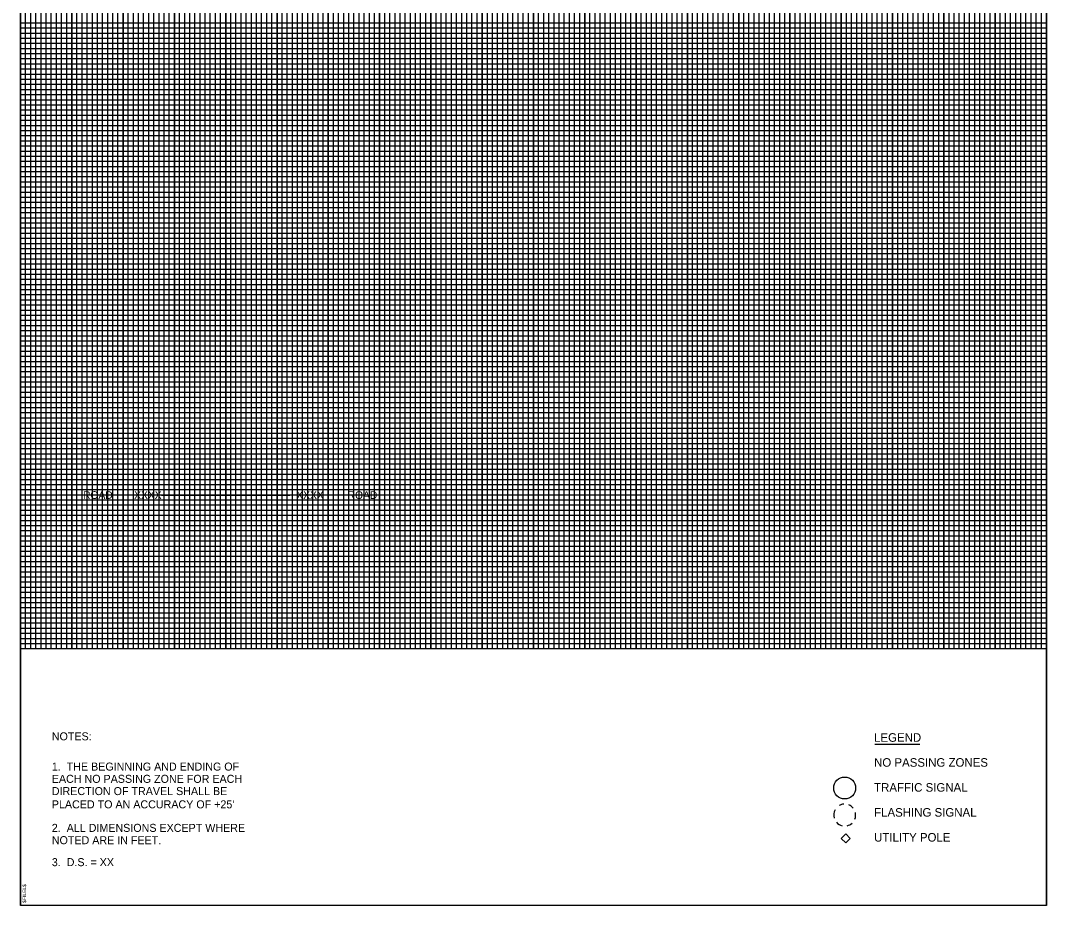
# Model space of a CAD drawing. Extents: x -6359 to 1641, y 3001 to 24737.
# Drawn here: x -6359 to 1641, y 10898 to 17798 of the extents above; entities that cross this region are included whole.
import ezdxf

# ---------------------------------------------------------------- set-up
doc = ezdxf.new("R2010")
doc.units = 0
for name, color, linetype in [('_grid', 7, 'Continuous'), ('_Notes', 7, 'Continuous'), ('Border', 7, 'Continuous'), ('TB - ON', 7, 'Continuous'), ('Title Block', 7, 'Continuous')]:
    doc.layers.add(name, color=color, linetype=linetype)

msp = doc.modelspace()

# ---------------------------------------------------------------- linework, layer by layer
at = {"layer": '_grid'}
for p, q in [((-6358.7, 21698.2), (-6358.7, 12898.2)), ((-6318.7, 12898.2), (-6318.7, 21698.2)), ((-6278.7, 12898.2), (-6278.7, 21698.2)), ((-6238.7, 12898.2), (-6238.7, 21698.2)), ((-6198.7, 12898.2), (-6198.7, 21698.2)), ((-6158.7, 12898.2), (-6158.7, 21698.2)), ((-6118.7, 12898.2), (-6118.7, 21698.2)), ((-6078.7, 12898.2), (-6078.7, 21698.2)), ((-6038.7, 12898.2), (-6038.7, 21698.2)), ((-5998.7, 12898.2), (-5998.7, 21698.2)), ((-5958.7, 21698.2), (-5958.7, 12898.2)), ((-5958.7, 12898.2), (-5958.7, 21698.2)), ((-5918.7, 12898.2), (-5918.7, 21698.2)), ((-5878.7, 12898.2), (-5878.7, 21698.2)), ((-5838.7, 12898.2), (-5838.7, 21698.2)), ((-5798.7, 12898.2), (-5798.7, 21698.2)), ((-5758.7, 12898.2), (-5758.7, 21698.2)), ((-5718.7, 12898.2), (-5718.7, 21698.2)), ((-5678.7, 12898.2), (-5678.7, 21698.2)), ((-5638.7, 12898.2), (-5638.7, 21698.2)), ((-5598.7, 12898.2), (-5598.7, 21698.2)), ((-5558.7, 21698.2), (-5558.7, 12898.2)), ((-5558.7, 12898.2), (-5558.7, 21698.2)), ((-5518.7, 12898.2), (-5518.7, 21698.2)), ((-5478.7, 12898.2), (-5478.7, 21698.2)), ((-5438.7, 12898.2), (-5438.7, 21698.2)), ((-5398.7, 12898.2), (-5398.7, 21698.2)), ((-5358.7, 12898.2), (-5358.7, 21698.2)), ((-5318.7, 12898.2), (-5318.7, 21698.2)), ((-5278.7, 12898.2), (-5278.7, 21698.2)), ((-5238.7, 12898.2), (-5238.7, 21698.2)), ((-5198.7, 12898.2), (-5198.7, 21698.2)), ((-5158.7, 21698.2), (-5158.7, 12898.2)), ((-5158.7, 12898.2), (-5158.7, 21698.2)), ((-5118.7, 12898.2), (-5118.7, 21698.2)), ((-5078.7, 12898.2), (-5078.7, 21698.2)), ((-5038.7, 12898.2), (-5038.7, 21698.2)), ((-4998.7, 12898.2), (-4998.7, 21698.2)), ((-4958.7, 12898.2), (-4958.7, 21698.2)), ((-4918.7, 12898.2), (-4918.7, 21698.2)), ((-4878.7, 12898.2), (-4878.7, 21698.2)), ((-4838.7, 12898.2), (-4838.7, 21698.2)), ((-4798.7, 12898.2), (-4798.7, 21698.2)), ((-4758.7, 21698.2), (-4758.7, 12898.2)), ((-4758.7, 12898.2), (-4758.7, 21698.2)), ((-4718.7, 12898.2), (-4718.7, 21698.2)), ((-4678.7, 12898.2), (-4678.7, 21698.2)), ((-4638.7, 12898.2), (-4638.7, 21698.2)), ((-4598.7, 12898.2), (-4598.7, 21698.2)), ((-4558.7, 12898.2), (-4558.7, 21698.2)), ((-4518.7, 12898.2), (-4518.7, 21698.2)), ((-4478.7, 12898.2), (-4478.7, 21698.2)), ((-4438.7, 12898.2), (-4438.7, 21698.2)), ((-4398.7, 12898.2), (-4398.7, 21698.2)), ((-4358.7, 21698.2), (-4358.7, 12898.2)), ((-4358.7, 12898.2), (-4358.7, 21698.2)), ((-4318.7, 12898.2), (-4318.7, 21698.2)), ((-4278.7, 12898.2), (-4278.7, 21698.2)), ((-4238.7, 12898.2), (-4238.7, 21698.2)), ((-4198.7, 12898.2), (-4198.7, 21698.2)), ((-4158.7, 12898.2), (-4158.7, 21698.2)), ((-4118.7, 12898.2), (-4118.7, 21698.2)), ((-4078.7, 12898.2), (-4078.7, 21698.2)), ((-4038.7, 12898.2), (-4038.7, 21698.2)), ((-3998.7, 12898.2), (-3998.7, 21698.2)), ((-3958.7, 21698.2), (-3958.7, 12898.2)), ((-3958.7, 12898.2), (-3958.7, 21698.2)), ((-3918.7, 12898.2), (-3918.7, 21698.2)), ((-3878.7, 12898.2), (-3878.7, 21698.2)), ((-3838.7, 12898.2), (-3838.7, 21698.2)), ((-3798.7, 12898.2), (-3798.7, 21698.2)), ((-3758.7, 12898.2), (-3758.7, 21698.2)), ((-3718.7, 12898.2), (-3718.7, 21698.2)), ((-3678.7, 12898.2), (-3678.7, 21698.2)), ((-3638.7, 12898.2), (-3638.7, 21698.2)), ((-3598.7, 12898.2), (-3598.7, 21698.2)), ((-3558.7, 21698.2), (-3558.7, 12898.2)), ((-3558.7, 12898.2), (-3558.7, 21698.2)), ((-3518.7, 12898.2), (-3518.7, 21698.2)), ((-3478.7, 12898.2), (-3478.7, 21698.2)), ((-3438.7, 12898.2), (-3438.7, 21698.2)), ((-3398.7, 12898.2), (-3398.7, 21698.2)), ((-3358.7, 12898.2), (-3358.7, 21698.2)), ((-3318.7, 12898.2), (-3318.7, 21698.2)), ((-3278.7, 12898.2), (-3278.7, 21698.2)), ((-3238.7, 12898.2), (-3238.7, 21698.2)), ((-3198.7, 12898.2), (-3198.7, 21698.2)), ((-3158.7, 21698.2), (-3158.7, 12898.2)), ((-3158.7, 12898.2), (-3158.7, 21698.2)), ((-3118.7, 12898.2), (-3118.7, 21698.2)), ((-3078.7, 12898.2), (-3078.7, 21698.2)), ((-3038.7, 12898.2), (-3038.7, 21698.2)), ((-2998.7, 12898.2), (-2998.7, 21698.2)), ((-2958.7, 12898.2), (-2958.7, 21698.2)), ((-2918.7, 12898.2), (-2918.7, 21698.2)), ((-2878.7, 12898.2), (-2878.7, 21698.2)), ((-2838.7, 12898.2), (-2838.7, 21698.2)), ((-2798.7, 12898.2), (-2798.7, 21698.2)), ((-2758.7, 21698.2), (-2758.7, 12898.2)), ((-2758.7, 12898.2), (-2758.7, 21698.2)), ((-2718.7, 12898.2), (-2718.7, 21698.2)), ((-2678.7, 12898.2), (-2678.7, 21698.2)), ((-2638.7, 12898.2), (-2638.7, 21698.2)), ((-2598.7, 12898.2), (-2598.7, 21698.2)), ((-2558.7, 12898.2), (-2558.7, 21698.2)), ((-2518.7, 12898.2), (-2518.7, 21698.2)), ((-2478.7, 12898.2), (-2478.7, 21698.2)), ((-2438.7, 12898.2), (-2438.7, 21698.2)), ((-2398.7, 12898.2), (-2398.7, 21698.2)), ((-2358.7, 21698.2), (-2358.7, 12898.2)), ((-2358.7, 12898.2), (-2358.7, 21698.2)), ((-2318.7, 12898.2), (-2318.7, 21698.2)), ((-2278.7, 12898.2), (-2278.7, 21698.2)), ((-2238.7, 12898.2), (-2238.7, 21698.2)), ((-2198.7, 12898.2), (-2198.7, 21698.2)), ((-2158.7, 12898.2), (-2158.7, 21698.2)), ((-2118.7, 12898.2), (-2118.7, 21698.2)), ((-2078.7, 12898.2), (-2078.7, 21698.2)), ((-2038.7, 12898.2), (-2038.7, 21698.2)), ((-1998.7, 12898.2), (-1998.7, 21698.2)), ((-1958.7, 21698.2), (-1958.7, 12898.2)), ((-1958.7, 12898.2), (-1958.7, 21698.2)), ((-1918.7, 12898.2), (-1918.7, 21698.2)), ((-1878.7, 12898.2), (-1878.7, 21698.2)), ((-1838.7, 12898.2), (-1838.7, 21698.2)), ((-1798.7, 12898.2), (-1798.7, 21698.2)), ((-1758.7, 12898.2), (-1758.7, 21698.2)), ((-1718.7, 12898.2), (-1718.7, 21698.2)), ((-1678.7, 12898.2), (-1678.7, 21698.2)), ((-1638.7, 12898.2), (-1638.7, 21698.2)), ((-1598.7, 12898.2), (-1598.7, 21698.2)), ((-1558.7, 21698.2), (-1558.7, 12898.2)), ((-1558.7, 12898.2), (-1558.7, 21698.2)), ((-1518.7, 12898.2), (-1518.7, 21698.2)), ((-1478.7, 12898.2), (-1478.7, 21698.2)), ((-1438.7, 12898.2), (-1438.7, 21698.2)), ((-1398.7, 12898.2), (-1398.7, 21698.2)), ((-1358.7, 12898.2), (-1358.7, 21698.2)), ((-1318.7, 12898.2), (-1318.7, 21698.2)), ((-1278.7, 12898.2), (-1278.7, 21698.2)), ((-1238.7, 12898.2), (-1238.7, 21698.2)), ((-1198.7, 12898.2), (-1198.7, 21698.2)), ((-1158.7, 21698.2), (-1158.7, 12898.2)), ((-1158.7, 12898.2), (-1158.7, 21698.2)), ((-1118.7, 12898.2), (-1118.7, 21698.2)), ((-1078.7, 12898.2), (-1078.7, 21698.2)), ((-1038.7, 12898.2), (-1038.7, 21698.2)), ((-998.7, 12898.2), (-998.7, 21698.2)), ((-958.7, 12898.2), (-958.7, 21698.2)), ((-918.7, 12898.2), (-918.7, 21698.2)), ((-878.7, 12898.2), (-878.7, 21698.2)), ((-838.7, 12898.2), (-838.7, 21698.2)), ((-798.7, 12898.2), (-798.7, 21698.2)), ((-758.7, 21698.2), (-758.7, 12898.2)), ((-758.7, 12898.2), (-758.7, 21698.2)), ((-718.7, 12898.2), (-718.7, 21698.2)), ((-678.7, 12898.2), (-678.7, 21698.2)), ((-638.7, 12898.2), (-638.7, 21698.2)), ((-598.7, 12898.2), (-598.7, 21698.2)), ((-558.7, 12898.2), (-558.7, 21698.2)), ((-518.7, 12898.2), (-518.7, 21698.2)), ((-478.7, 12898.2), (-478.7, 21698.2)), ((-438.7, 12898.2), (-438.7, 21698.2)), ((-398.7, 12898.2), (-398.7, 21698.2)), ((-358.7, 21698.2), (-358.7, 12898.2)), ((-358.7, 12898.2), (-358.7, 21698.2)), ((-318.7, 12898.2), (-318.7, 21698.2)), ((-278.7, 12898.2), (-278.7, 21698.2)), ((-238.7, 12898.2), (-238.7, 21698.2)), ((-198.7, 12898.2), (-198.7, 21698.2)), ((-158.7, 12898.2), (-158.7, 21698.2)), ((-118.7, 12898.2), (-118.7, 21698.2)), ((-78.7, 12898.2), (-78.7, 21698.2)), ((-38.7, 12898.2), (-38.7, 21698.2)), ((1.3, 12898.2), (1.3, 21698.2)), ((41.3, 21698.2), (41.3, 12898.2)), ((41.3, 12898.2), (41.3, 21698.2)), ((81.3, 12898.2), (81.3, 21698.2)), ((121.3, 12898.2), (121.3, 21698.2)), ((161.3, 12898.2), (161.3, 21698.2)), ((201.3, 12898.2), (201.3, 21698.2)), ((241.3, 12898.2), (241.3, 21698.2)), ((281.3, 12898.2), (281.3, 21698.2)), ((321.3, 12898.2), (321.3, 21698.2)), ((361.3, 12898.2), (361.3, 21698.2)), ((401.3, 12898.2), (401.3, 21698.2)), ((441.3, 21698.2), (441.3, 12898.2)), ((441.3, 12898.2), (441.3, 21698.2)), ((481.3, 12898.2), (481.3, 21698.2)), ((521.3, 12898.2), (521.3, 21698.2)), ((561.3, 12898.2), (561.3, 21698.2)), ((601.3, 12898.2), (601.3, 21698.2)), ((641.3, 12898.2), (641.3, 21698.2)), ((681.3, 12898.2), (681.3, 21698.2)), ((721.3, 12898.2), (721.3, 21698.2)), ((761.3, 12898.2), (761.3, 21698.2)), ((801.3, 12898.2), (801.3, 21698.2)), ((841.3, 21698.2), (841.3, 12898.2)), ((841.3, 12898.2), (841.3, 21698.2)), ((881.3, 12898.2), (881.3, 21698.2)), ((921.3, 12898.2), (921.3, 21698.2)), ((961.3, 12898.2), (961.3, 21698.2)), ((1001.3, 12898.2), (1001.3, 21698.2)), ((1041.3, 12898.2), (1041.3, 21698.2)), ((1081.3, 12898.2), (1081.3, 21698.2)), ((1121.3, 12898.2), (1121.3, 21698.2)), ((1161.3, 12898.2), (1161.3, 21698.2)), ((1201.3, 12898.2), (1201.3, 21698.2)), ((1241.3, 21698.2), (1241.3, 12898.2)), ((1241.3, 12898.2), (1241.3, 21698.2)), ((1281.3, 12898.2), (1281.3, 21698.2)), ((1321.3, 12898.2), (1321.3, 21698.2)), ((1361.3, 12898.2), (1361.3, 21698.2)), ((1401.3, 12898.2), (1401.3, 21698.2)), ((1441.3, 12898.2), (1441.3, 21698.2)), ((1481.3, 12898.2), (1481.3, 21698.2)), ((1521.3, 12898.2), (1521.3, 21698.2)), ((1561.3, 12898.2), (1561.3, 21698.2)), ((1601.3, 12898.2), (1601.3, 21698.2)), ((1641.3, 12898.2), (1641.3, 21698.2)), ((1641.3, 21698.2), (1641.3, 12898.2)), ((1641.3, 17778.2), (-6358.7, 17778.2)), ((1641.3, 17738.2), (-6358.7, 17738.2)), ((1641.3, 17698.2), (-6358.7, 17698.2)), ((1641.3, 17698.2), (-6358.7, 17698.2)), ((1641.3, 17658.2), (-6358.7, 17658.2)), ((1641.3, 17618.2), (-6358.7, 17618.2)), ((1641.3, 17578.2), (-6358.7, 17578.2)), ((1641.3, 17538.2), (-6358.7, 17538.2)), ((1641.3, 17498.2), (-6358.7, 17498.2)), ((1641.3, 17458.2), (-6358.7, 17458.2)), ((1641.3, 17418.2), (-6358.7, 17418.2)), ((1641.3, 17378.2), (-6358.7, 17378.2)), ((1641.3, 17338.2), (-6358.7, 17338.2)), ((1641.3, 17298.2), (-6358.7, 17298.2)), ((1641.3, 17298.2), (-6358.7, 17298.2)), ((1641.3, 17258.2), (-6358.7, 17258.2)), ((1641.3, 17218.2), (-6358.7, 17218.2)), ((1641.3, 17178.2), (-6358.7, 17178.2)), ((1641.3, 17138.2), (-6358.7, 17138.2)), ((1641.3, 17098.2), (-6358.7, 17098.2)), ((1641.3, 17058.2), (-6358.7, 17058.2)), ((1641.3, 17018.2), (-6358.7, 17018.2)), ((1641.3, 16978.2), (-6358.7, 16978.2)), ((1641.3, 16938.2), (-6358.7, 16938.2)), ((1641.3, 16898.2), (-6358.7, 16898.2)), ((1641.3, 16898.2), (-6358.7, 16898.2)), ((1641.3, 16858.2), (-6358.7, 16858.2)), ((1641.3, 16818.2), (-6358.7, 16818.2)), ((1641.3, 16778.2), (-6358.7, 16778.2)), ((1641.3, 16738.2), (-6358.7, 16738.2)), ((1641.3, 16698.2), (-6358.7, 16698.2)), ((1641.3, 16658.2), (-6358.7, 16658.2)), ((1641.3, 16618.2), (-6358.7, 16618.2)), ((1641.3, 16578.2), (-6358.7, 16578.2)), ((1641.3, 16538.2), (-6358.7, 16538.2)), ((1641.3, 16498.2), (-6358.7, 16498.2)), ((1641.3, 16498.2), (-6358.7, 16498.2)), ((1641.3, 16458.2), (-6358.7, 16458.2)), ((1641.3, 16418.2), (-6358.7, 16418.2)), ((1641.3, 16378.2), (-6358.7, 16378.2)), ((1641.3, 16338.2), (-6358.7, 16338.2)), ((1641.3, 16298.2), (-6358.7, 16298.2)), ((1641.3, 16258.2), (-6358.7, 16258.2)), ((1641.3, 16218.2), (-6358.7, 16218.2)), ((1641.3, 16178.2), (-6358.7, 16178.2)), ((1641.3, 16138.2), (-6358.7, 16138.2)), ((1641.3, 16098.2), (-6358.7, 16098.2)), ((1641.3, 16098.2), (-6358.7, 16098.2)), ((1641.3, 16058.2), (-6358.7, 16058.2)), ((1641.3, 16018.2), (-6358.7, 16018.2)), ((1641.3, 15978.2), (-6358.7, 15978.2)), ((1641.3, 15938.2), (-6358.7, 15938.2)), ((1641.3, 15898.2), (-6358.7, 15898.2)), ((1641.3, 15858.2), (-6358.7, 15858.2)), ((1641.3, 15818.2), (-6358.7, 15818.2)), ((1641.3, 15778.2), (-6358.7, 15778.2)), ((1641.3, 15738.2), (-6358.7, 15738.2)), ((1641.3, 15698.2), (-6358.7, 15698.2)), ((1641.3, 15698.2), (-6358.7, 15698.2)), ((1641.3, 15658.2), (-6358.7, 15658.2)), ((1641.3, 15618.2), (-6358.7, 15618.2)), ((1641.3, 15578.2), (-6358.7, 15578.2)), ((1641.3, 15538.2), (-6358.7, 15538.2)), ((1641.3, 15498.2), (-6358.7, 15498.2)), ((1641.3, 15458.2), (-6358.7, 15458.2)), ((1641.3, 15418.2), (-6358.7, 15418.2)), ((1641.3, 15378.2), (-6358.7, 15378.2)), ((1641.3, 15338.2), (-6358.7, 15338.2)), ((1641.3, 15298.2), (-6358.7, 15298.2)), ((1641.3, 15298.2), (-6358.7, 15298.2)), ((1641.3, 15258.2), (-6358.7, 15258.2)), ((1641.3, 15218.2), (-6358.7, 15218.2)), ((1641.3, 15178.2), (-6358.7, 15178.2)), ((1641.3, 15138.2), (-6358.7, 15138.2)), ((1641.3, 15098.2), (-6358.7, 15098.2)), ((1641.3, 15058.2), (-6358.7, 15058.2)), ((1641.3, 15018.2), (-6358.7, 15018.2)), ((1641.3, 14978.2), (-6358.7, 14978.2)), ((1641.3, 14938.2), (-6358.7, 14938.2)), ((1641.3, 14898.2), (-6358.7, 14898.2)), ((1641.3, 14898.2), (-6358.7, 14898.2)), ((1641.3, 14858.2), (-6358.7, 14858.2)), ((1641.3, 14818.2), (-6358.7, 14818.2)), ((1641.3, 14778.2), (-6358.7, 14778.2)), ((1641.3, 14738.2), (-6358.7, 14738.2)), ((1641.3, 14698.2), (-6358.7, 14698.2)), ((1641.3, 14658.2), (-6358.7, 14658.2)), ((1641.3, 14618.2), (-6358.7, 14618.2)), ((1641.3, 14578.2), (-6358.7, 14578.2)), ((1641.3, 14538.2), (-6358.7, 14538.2)), ((1641.3, 14498.2), (-6358.7, 14498.2)), ((1641.3, 14498.2), (-6358.7, 14498.2)), ((1641.3, 14458.2), (-6358.7, 14458.2)), ((1641.3, 14418.2), (-6358.7, 14418.2)), ((1641.3, 14378.2), (-6358.7, 14378.2)), ((1641.3, 14338.2), (-6358.7, 14338.2)), ((1641.3, 14298.2), (-6358.7, 14298.2)), ((1641.3, 14258.2), (-6358.7, 14258.2)), ((1641.3, 14218.2), (-6358.7, 14218.2)), ((1641.3, 14178.2), (-6358.7, 14178.2)), ((1641.3, 14138.2), (-6358.7, 14138.2)), ((1641.3, 14098.2), (-6358.7, 14098.2)), ((1641.3, 14098.2), (-6358.7, 14098.2)), ((1641.3, 14058.2), (-6358.7, 14058.2)), ((1641.3, 14018.2), (-6358.7, 14018.2)), ((1641.3, 13978.2), (-6358.7, 13978.2)), ((1641.3, 13938.2), (-6358.7, 13938.2)), ((1641.3, 13898.2), (-6358.7, 13898.2)), ((1641.3, 13858.2), (-6358.7, 13858.2)), ((1641.3, 13818.2), (-6358.7, 13818.2)), ((1641.3, 13778.2), (-6358.7, 13778.2)), ((1641.3, 13738.2), (-6358.7, 13738.2)), ((1641.3, 13698.2), (-6358.7, 13698.2)), ((1641.3, 13698.2), (-6358.7, 13698.2)), ((1641.3, 13658.2), (-6358.7, 13658.2)), ((1641.3, 13618.2), (-6358.7, 13618.2)), ((1641.3, 13578.2), (-6358.7, 13578.2)), ((1641.3, 13538.2), (-6358.7, 13538.2)), ((1641.3, 13498.2), (-6358.7, 13498.2)), ((1641.3, 13458.2), (-6358.7, 13458.2)), ((1641.3, 13418.2), (-6358.7, 13418.2)), ((1641.3, 13378.2), (-6358.7, 13378.2)), ((1641.3, 13338.2), (-6358.7, 13338.2)), ((1641.3, 13298.2), (-6358.7, 13298.2)), ((1641.3, 13298.2), (-6358.7, 13298.2)), ((1641.3, 13258.2), (-6358.7, 13258.2)), ((1641.3, 13218.2), (-6358.7, 13218.2)), ((1641.3, 13178.2), (-6358.7, 13178.2)), ((1641.3, 13138.2), (-6358.7, 13138.2)), ((1641.3, 13098.2), (-6358.7, 13098.2)), ((1641.3, 13058.2), (-6358.7, 13058.2)), ((1641.3, 13018.2), (-6358.7, 13018.2)), ((1641.3, 12978.2), (-6358.7, 12978.2)), ((1641.3, 12938.2), (-6358.7, 12938.2)), ((1641.3, 12898.2), (-6358.7, 12898.2)), ((1641.3, 12898.2), (-6358.7, 12898.2))]:
    msp.add_line(p, q, dxfattribs=at)
at = {"layer": '_Notes'}
for p, q in [((-5259.2, 14098.2), (-4758.7, 14098.2)), ((-4758.7, 14098.2), (-4258.3, 14098.2))]:
    msp.add_line(p, q, dxfattribs=at)
at = {"layer": 'Border'}
for p, q in [((-6358.7, 24098.2), (-6358.7, 10898.2)), ((1641.3, 21698.2), (1641.3, 12898.2)), ((1641.3, 12898.2), (1641.3, 10898.2)), ((1641.3, 10898.2), (-6358.7, 10898.2))]:
    msp.add_line(p, q, dxfattribs=at)
at = {"layer": 'TB - ON'}
for q in [(1641.3, 12898.2), (-6358.7, 10898.2)]:
    msp.add_line((1641.3, 10898.2), q, dxfattribs=at)
at = {"layer": 'Title Block'}
for p, q in [((-6358.7, 10898.2), (-6358.7, 24098.2)), ((1641.3, 24098.2), (1641.3, 10898.2)), ((653.7, 12152.4), (301.6, 12152.4)), ((1641.3, 10898.2), (-6358.7, 10898.2))]:
    msp.add_line(p, q, dxfattribs=at)
msp.add_lwpolyline([(110.6, 11421), (75.9, 11386.3), (41.3, 11421), (75.9, 11455.7)], close=True, dxfattribs=at)
msp.add_circle((67.7, 11814.5), 85.4, dxfattribs=at)
for start, end in [(94.34369, 120.38652), (38.93931, 67.37155), (151.98801, 196.12857), (338.62004, 13.39203), (220.49019, 257.26023), (283.12018, 311.98481)]:
    msp.add_arc((67.7, 11603.4), 85.4, start, end, dxfattribs=at)

# ---------------------------------------------------------------- texts
at = {"layer": '_Notes'}
for s, p in [('ROAD', (-5871.6, 14068.2)), ('XXXX', (-5472.7, 14068.2)), ('XXXX', (-4208.3, 14068.2)), ('ROAD', (-3808.3, 14068.2))]:
    msp.add_text(s, height=60, dxfattribs=at).set_placement(p)
at = {"layer": 'TB - ON'}
msp.add_text('$FILEL$', height=28, rotation=90, dxfattribs=at).set_placement((-6314.9, 10919))
at = {"layer": 'Title Block'}
for s, height, p in [('NOTES:', 62.41, (-6114.7, 12185.8)), ('1.  THE BEGINNING AND ENDING OF', 62.407, (-6114.7, 11949.9)), ('EACH NO PASSING ZONE FOR EACH', 62.407, (-6114.7, 11854.4)), ('DIRECTION OF TRAVEL SHALL BE', 62.407, (-6114.7, 11758.9)), ("PLACED TO AN ACCURACY OF +25'", 62.407, (-6114.7, 11655.6)), ('2.  ALL DIMENSIONS EXCEPT WHERE', 62.407, (-6114.7, 11472.1)), ('NOTED ARE IN FEET.', 62.407, (-6114.7, 11376)), ('3.  D.S. = XX', 62.407, (-6114.7, 11204.8))]:
    msp.add_text(s, height=height, dxfattribs=at).set_placement(p)
for s, height, p in [('LEGEND', 66.76, (297, 12174.5)), ('NO PASSING ZONES', 66.764, (297, 11979.9)), ('TRAFFIC SIGNAL', 66.764, (297.1, 11785.3)), ('FLASHING SIGNAL', 66.764, (297.2, 11590.7)), ('UTILITY POLE', 66.764, (297.2, 11396.1))]:
    msp.add_text(s, height=height, rotation=0.01594, dxfattribs=at).set_placement(p)

doc.saveas('drawing.dxf')
